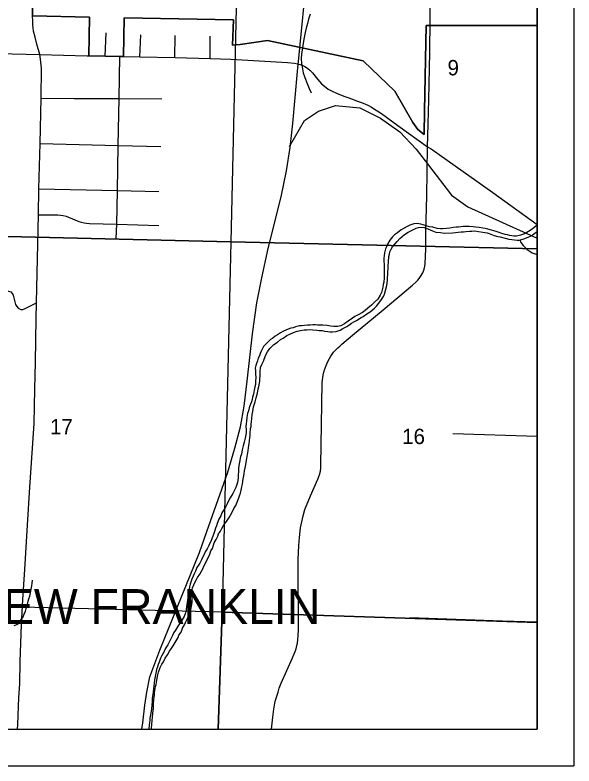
# Model space of a CAD drawing. Extents: x 0 to 34, y -5 to 22.
# Drawn here: x 7.476 to 9, y 14 to 16.047 of the extents above; entities that cross this region are included whole.
import ezdxf

# ---------------------------------------------------------------- set-up
doc = ezdxf.new("R2010")
doc.units = 0
for name, color, linetype in [('GM_X_City_Street', 7, 'Continuous'), ('GM_X_Corporation_Text', 7, 'Continuous'), ('GM_X_County_Road', 7, 'Continuous'), ('GM_X_Major_River', 7, 'Continuous'), ('GM_X_Minor_River', 7, 'Continuous'), ('GM_X_Rail_Line', 7, 'Continuous'), ('GM_X_Section', 7, 'Continuous'), ('GM_X_Section_Text', 7, 'Continuous'), ('GM_X_Township_Road', 7, 'Continuous'), ('GM_X_US_Route', 7, 'Continuous'), ('SC_Scratch2', 7, 'Continuous'), ('SH_Cut_Line', 7, 'Continuous'), ('SH_Data', 7, 'Continuous')]:
    doc.layers.add(name, color=color, linetype=linetype)

msp = doc.modelspace()

# ---------------------------------------------------------------- linework, layer by layer
at = {"layer": 'GM_X_City_Street'}
for points in [[(8.9, 15.4101), (8.9, 16.4107), (8.0868, 16.4255), (8.0646, 15.4287)], [(8.9, 14.3911), (8.9, 15.4101), (8.0646, 15.4287), (8.041, 14.419)], [(6.9745, 14.1), (8.0304, 14.1), (8.041, 14.419), (6.9822, 14.4457)], [(8.0304, 14.1), (8.9, 14.1), (8.9, 14.3911), (8.041, 14.419)]]:
    msp.add_lwpolyline(points, close=True, dxfattribs=at)
at = {"layer": 'GM_X_County_Road'}
for p, q in [((7.5439, 15.9397), (7.6724, 15.9357)), ((8.6006, 15.688), (8.6014, 15.7176))]:
    msp.add_line(p, q, dxfattribs=at)
for points in [[(8.6066, 15.9447), (8.6069, 15.9615), (8.6077, 16.0182), (8.6081, 16.1361), (8.6122, 16.2981), (8.6134, 16.3612), (8.6129, 16.3779)], [(7.5238, 16.047), (7.5244, 16.0747), (7.525, 16.0968), (7.5286, 16.2498), (7.5306, 16.3351)], [(7.5439, 15.9397), (7.5358, 15.9674), (7.5307, 15.9865), (7.5265, 16.0032), (7.5252, 16.012), (7.5243, 16.0205), (7.5243, 16.0309), (7.5237, 16.044), (7.5238, 16.047)], [(6.9889, 15.9539), (7.2426, 15.947), (7.5439, 15.9397)], [(7.535, 15.2621), (7.5384, 15.4231), (7.54, 15.5026), (7.5413, 15.5729), (7.5445, 15.6966), (7.547, 15.8205), (7.5482, 15.9022), (7.5468, 15.9185), (7.5457, 15.927), (7.5439, 15.9397)], [(7.6724, 15.9357), (7.6773, 15.9356), (7.7222, 15.9348), (7.7622, 15.9337), (7.772, 15.9336), (7.7731, 15.9336)], [(7.7731, 15.9336), (7.8165, 15.9333), (7.9119, 15.9309), (8.0077, 15.9284), (8.0643, 15.9268), (8.219, 15.9176), (8.2379, 15.9156), (8.2459, 15.9142), (8.2532, 15.9124), (8.2591, 15.9101), (8.2666, 15.9066), (8.2736, 15.9022), (8.2803, 15.8965), (8.2872, 15.8895), (8.3009, 15.8718), (8.3119, 15.8592), (8.3196, 15.8527), (8.3294, 15.8453), (8.3349, 15.8421), (8.3408, 15.8392), (8.3522, 15.8339), (8.3722, 15.8262), (8.3838, 15.8221), (8.3958, 15.8176), (8.407, 15.8135), (8.4184, 15.8095), (8.43, 15.8048), (8.4394, 15.8005), (8.4482, 15.7956), (8.461, 15.7877), (8.4749, 15.7783), (8.5197, 15.7457), (8.6006, 15.688)], [(8.6014, 15.7176), (8.6043, 15.8162), (8.6066, 15.9447)], [(8.1753, 14.1), (8.1754, 14.1001), (8.1788, 14.1327), (8.1819, 14.1552), (8.1847, 14.1712), (8.1866, 14.1796), (8.1892, 14.188), (8.1931, 14.2008), (8.1961, 14.212), (8.2018, 14.2254), (8.2328, 14.2951), (8.2371, 14.3055), (8.2397, 14.312), (8.2424, 14.3192), (8.2448, 14.3281), (8.2461, 14.3347), (8.2473, 14.3444), (8.2481, 14.3559), (8.2487, 14.3715), (8.2487, 14.3927), (8.2483, 14.5327), (8.2481, 14.5629), (8.2497, 14.6014), (8.2514, 14.623), (8.2542, 14.6489), (8.2613, 14.6815), (8.2664, 14.6994), (8.2815, 14.7363), (8.3019, 14.7815), (8.3066, 14.7939), (8.3088, 14.8033), (8.3096, 14.8121), (8.31, 14.8202), (8.3123, 14.9867), (8.3135, 15.0454), (8.3164, 15.0655), (8.3188, 15.0769), (8.3241, 15.092), (8.3298, 15.1045), (8.3371, 15.1167), (8.3445, 15.1277), (8.3559, 15.1401), (8.3622, 15.1456), (8.367, 15.1502), (8.3964, 15.1745), (8.4794, 15.2434), (8.5602, 15.3109), (8.5696, 15.3198), (8.5741, 15.3241), (8.578, 15.3292), (8.5816, 15.3341), (8.5876, 15.3439), (8.5912, 15.3545), (8.5933, 15.3622), (8.5941, 15.3689), (8.5961, 15.4099), (8.5961, 15.4557), (8.5986, 15.5531), (8.6006, 15.688)], [(8.6006, 15.688), (8.6106, 15.6819), (8.7785, 15.5635), (8.9, 15.4759)], [(7.4833, 14.1), (7.4837, 14.1131), (7.4849, 14.1379), (7.4868, 14.1864), (7.4888, 14.2237), (7.4904, 14.285), (7.4939, 14.3849), (7.4971, 14.4534), (7.5029, 14.5355), (7.5104, 14.6563), (7.5167, 14.7596), (7.5212, 14.8262), (7.5279, 14.9338), (7.53, 15.0275), (7.5316, 15.1011), (7.534, 15.2197), (7.535, 15.2621)]]:
    msp.add_lwpolyline(points, dxfattribs=at)
at = {"layer": 'GM_X_Major_River'}
for points in [[(8.9, 15.4741), (8.8956, 15.4714), (8.8858, 15.4637), (8.8756, 15.4568), (8.865, 15.4506), (8.8544, 15.447), (8.8431, 15.4443), (8.8362, 15.4442), (8.8252, 15.4463), (8.8187, 15.4474), (8.8127, 15.4489), (8.8032, 15.4514), (8.7933, 15.4547), (8.7875, 15.4566), (8.775, 15.4603), (8.7655, 15.4632), (8.7582, 15.4654), (8.7514, 15.4661), (8.7415, 15.4675), (8.7316, 15.4685), (8.7248, 15.4692), (8.7145, 15.4706), (8.7035, 15.4705), (8.6979, 15.4701), (8.6914, 15.4696), (8.685, 15.4688), (8.6789, 15.4684), (8.6702, 15.4675), (8.6611, 15.4663), (8.6527, 15.4647), (8.6414, 15.4638), (8.6357, 15.4641), (8.6273, 15.4655), (8.6155, 15.4688), (8.6064, 15.4699), (8.5969, 15.4724), (8.5889, 15.475), (8.5828, 15.4772), (8.5714, 15.4786), (8.5631, 15.4782), (8.5521, 15.4739), (8.5453, 15.4707), (8.5291, 15.4611), (8.5185, 15.4537), (8.511, 15.448), (8.5053, 15.4422), (8.4982, 15.433), (8.4919, 15.4227), (8.4889, 15.4151), (8.4863, 15.4093), (8.4838, 15.3987), (8.4827, 15.3914), (8.482, 15.3846), (8.4822, 15.3591), (8.4823, 15.3523), (8.4825, 15.331), (8.4815, 15.3188), (8.48, 15.3124), (8.4786, 15.3051), (8.4768, 15.2983), (8.4749, 15.2907), (8.4712, 15.283), (8.4656, 15.2727), (8.4566, 15.2639), (8.4476, 15.2558), (8.4378, 15.2481), (8.4303, 15.2419), (8.4231, 15.2362), (8.4114, 15.23), (8.4027, 15.2249), (8.3963, 15.2207), (8.3846, 15.2129), (8.3741, 15.2052), (8.3642, 15.2002), (8.3552, 15.1978), (8.3453, 15.1981), (8.3362, 15.1991), (8.3271, 15.2009)], [(8.3515, 15.1841), (8.3621, 15.188), (8.3696, 15.1923), (8.3806, 15.1981), (8.3866, 15.202), (8.3938, 15.2066), (8.4002, 15.2108), (8.407, 15.2147), (8.4194, 15.2221), (8.4255, 15.2255), (8.4349, 15.2321), (8.4443, 15.2383), (8.456, 15.2483), (8.462, 15.2533), (8.4703, 15.2652), (8.4751, 15.2717), (8.4804, 15.2797), (8.4837, 15.2858), (8.487, 15.2995), (8.4885, 15.306), (8.4903, 15.3151), (8.4913, 15.325), (8.4926, 15.3456), (8.4933, 15.3577), (8.4936, 15.3646), (8.4939, 15.3733), (8.4956, 15.3885), (8.4971, 15.3954), (8.4982, 15.4011), (8.5019, 15.4084), (8.5056, 15.4152), (8.512, 15.4225), (8.5176, 15.4294), (8.5255, 15.4382), (8.5379, 15.4483), (8.5481, 15.4548), (8.5606, 15.4614), (8.5696, 15.4657), (8.5761, 15.4677), (8.5855, 15.4685), (8.5912, 15.4674), (8.5973, 15.4656), (8.608, 15.4619), (8.6141, 15.4589), (8.6236, 15.4552), (8.6358, 15.4538), (8.6464, 15.4528), (8.6688, 15.4531), (8.6768, 15.4539), (8.684, 15.4547), (8.6923, 15.4556), (8.6987, 15.4564), (8.7048, 15.4572), (8.7154, 15.4577), (8.7211, 15.4582), (8.7295, 15.4583), (8.7393, 15.4572), (8.7511, 15.4551), (8.7568, 15.454), (8.7633, 15.4529), (8.7736, 15.45), (8.7823, 15.4463), (8.7926, 15.4437), (8.7987, 15.4426), (8.8124, 15.4386), (8.8223, 15.4364), (8.8306, 15.435), (8.8375, 15.4343), (8.8447, 15.4336), (8.8508, 15.4337), (8.8568, 15.4349), (8.8629, 15.4365), (8.8754, 15.4412), (8.8829, 15.4454), (8.8935, 15.4524), (8.9, 15.4569)], [(8.3271, 15.2009), (8.3149, 15.202), (8.3012, 15.2018), (8.2955, 15.2021), (8.2883, 15.2021), (8.2807, 15.202), (8.2735, 15.2015), (8.2656, 15.2007), (8.2572, 15.2002), (8.2516, 15.1994), (8.2409, 15.1974), (8.2341, 15.1946), (8.2277, 15.1931), (8.2164, 15.1888), (8.2065, 15.1841), (8.2001, 15.1806), (8.1918, 15.1752), (8.1854, 15.1717), (8.179, 15.1663), (8.173, 15.1621), (8.1628, 15.1528), (8.1538, 15.1433), (8.1471, 15.1303), (8.1445, 15.1242), (8.1423, 15.1184), (8.1389, 15.1116), (8.1371, 15.1047), (8.1341, 15.0974), (8.1323, 15.0917), (8.1312, 15.0841), (8.1313, 15.0784), (8.1318, 15.0678), (8.1322, 15.0598), (8.132, 15.0484), (8.1313, 15.04), (8.1302, 15.0336), (8.1284, 15.0241), (8.1262, 15.0138), (8.124, 15.005), (8.1226, 14.9993), (8.1204, 14.9924), (8.1185, 14.986), (8.1148, 14.9764), (8.1122, 14.9684), (8.11, 14.9604), (8.1083, 14.9497), (8.1072, 14.9402), (8.1061, 14.9322), (8.1054, 14.9262), (8.1063, 14.9167), (8.106, 14.9079), (8.1046, 14.8984), (8.1024, 14.8897), (8.1006, 14.8824), (8.0984, 14.8729), (8.0958, 14.8622), (8.0933, 14.8504), (8.0911, 14.8436), (8.0882, 14.8283), (8.0867, 14.8188), (8.0857, 14.8112), (8.0854, 14.8036), (8.0847, 14.7926), (8.0844, 14.7857), (8.0823, 14.7728), (8.0778, 14.7591), (8.0741, 14.7522), (8.0697, 14.7426), (8.0629, 14.7308), (8.0585, 14.7224), (8.0547, 14.7144), (8.0495, 14.7059), (8.045, 14.6979), (8.0402, 14.6903), (8.0369, 14.6815), (8.032, 14.6731), (8.0276, 14.6613), (8.025, 14.6548), (8.0231, 14.6487), (8.0205, 14.6422), (8.018, 14.6338), (8.015, 14.6266), (8.0109, 14.6147), (8.0042, 14.601), (7.9998, 14.5922), (7.9949, 14.5838), (7.9916, 14.5765), (7.9882, 14.57), (7.9841, 14.562), (7.9797, 14.5532), (7.9763, 14.5475), (7.9718, 14.5414), (7.9681, 14.5314), (7.9648, 14.5234), (7.9618, 14.5173), (7.9581, 14.5093), (7.9555, 14.5013), (7.954, 14.4952), (7.9522, 14.4883), (7.9501, 14.4746), (7.949, 14.4682)], [(7.9492, 14.4085), (7.9529, 14.4184), (7.9551, 14.4268), (7.9573, 14.436), (7.9587, 14.4455), (7.9584, 14.4743), (7.9591, 14.4801), (7.9602, 14.4858), (7.9632, 14.4934), (7.9676, 14.5022), (7.971, 14.5079), (7.974, 14.5137), (7.9799, 14.5228), (7.9848, 14.5312), (7.9878, 14.537), (7.9907, 14.5446), (7.9971, 14.5568), (8.003, 14.5687), (8.006, 14.5748), (8.0101, 14.5862), (8.0142, 14.5931), (8.0175, 14.6015), (8.0193, 14.6087), (8.0246, 14.6172), (8.0287, 14.6263), (8.0309, 14.6328), (8.0365, 14.6397), (8.0402, 14.6477), (8.0458, 14.6573), (8.0526, 14.6668), (8.06, 14.6776), (8.0638, 14.6837), (8.0697, 14.6955), (8.0731, 14.702), (8.0779, 14.7104), (8.0813, 14.7192), (8.0865, 14.731), (8.0879, 14.7368), (8.0909, 14.7432), (8.0927, 14.752), (8.0945, 14.7608), (8.0963, 14.768), (8.0974, 14.7764), (8.0981, 14.7828), (8.0999, 14.7905), (8.1006, 14.7977), (8.1021, 14.8049), (8.1046, 14.816), (8.1064, 14.8285), (8.1078, 14.8384), (8.1096, 14.8487), (8.1114, 14.8594), (8.1128, 14.8685), (8.1146, 14.8784), (8.1153, 14.8871), (8.1164, 14.8944), (8.1171, 14.9008), (8.1174, 14.9069), (8.1184, 14.9195), (8.1195, 14.9252), (8.1198, 14.9313), (8.1205, 14.9377), (8.1216, 14.9469), (8.1226, 14.9583), (8.1244, 14.9666), (8.1266, 14.9792), (8.131, 14.9929), (8.1339, 15.0036), (8.1376, 15.0162), (8.1394, 15.0276), (8.1416, 15.0379), (8.1437, 15.0501), (8.1443, 15.0691), (8.1442, 15.0751), (8.1456, 15.0858), (8.1486, 15.0946), (8.1531, 15.1037), (8.159, 15.119), (8.1646, 15.1289), (8.1709, 15.1377), (8.1815, 15.1485), (8.192, 15.1554), (8.1999, 15.1627), (8.2075, 15.1666), (8.2169, 15.1732), (8.2252, 15.1771), (8.2354, 15.1814), (8.2449, 15.1849), (8.254, 15.1869), (8.2642, 15.1885), (8.2721, 15.1893), (8.2782, 15.1894), (8.2881, 15.1891), (8.2987, 15.1881), (8.3052, 15.1874), (8.3139, 15.1867), (8.3196, 15.1853), (8.3287, 15.1842), (8.3344, 15.1835), (8.3416, 15.1836), (8.3515, 15.1841)], [(7.949, 14.4682), (7.9472, 14.4579), (7.9454, 14.4453), (7.944, 14.4351), (7.9426, 14.4248), (7.9411, 14.4176), (7.9374, 14.4073), (7.9303, 14.3958), (7.9262, 14.3893), (7.9217, 14.3835), (7.9139, 14.3698), (7.9094, 14.364), (7.9057, 14.356), (7.9012, 14.3465), (7.8956, 14.3361), (7.8926, 14.3304), (7.8859, 14.3189), (7.8826, 14.3121), (7.8792, 14.3059), (7.8759, 14.2995), (7.8729, 14.2937), (7.8692, 14.2827), (7.8666, 14.2762), (7.8648, 14.2701), (7.8622, 14.2628), (7.86, 14.2529), (7.8582, 14.2442), (7.8564, 14.235), (7.8553, 14.2251), (7.8543, 14.2183), (7.8539, 14.2111), (7.8525, 14.2012), (7.8515, 14.1947), (7.8504, 14.1848), (7.8501, 14.1761), (7.8495, 14.1654), (7.8484, 14.1555), (7.8473, 14.1491), (7.8455, 14.1392), (7.8441, 14.13), (7.8434, 14.1243), (7.8427, 14.1182), (7.8416, 14.1114), (7.8406, 14.1019), (7.8403, 14.1)], [(7.8483, 14.1), (7.8485, 14.1031), (7.8492, 14.113), (7.8499, 14.1244), (7.8505, 14.1331), (7.8516, 14.1434), (7.8533, 14.1586), (7.854, 14.1681), (7.855, 14.1818), (7.856, 14.1925), (7.8567, 14.1982), (7.8574, 14.2054), (7.8592, 14.2164), (7.8607, 14.2225), (7.8625, 14.2332), (7.8635, 14.2397), (7.8653, 14.2484), (7.8676, 14.2561), (7.872, 14.2683), (7.8768, 14.2778), (7.8806, 14.2843), (7.8858, 14.2935), (7.8914, 14.303), (7.8977, 14.3126), (7.9022, 14.3195), (7.9075, 14.3271), (7.9157, 14.3409), (7.9205, 14.3501), (7.9224, 14.3562), (7.9287, 14.365), (7.9324, 14.376), (7.9384, 14.3848), (7.9406, 14.3913), (7.9451, 14.4005), (7.9492, 14.4085)]]:
    msp.add_lwpolyline(points, dxfattribs=at)
at = {"layer": 'GM_X_Minor_River'}
for points in [[(8.2806, 16.0497), (8.2761, 16.0356), (8.2732, 16.0241), (8.2699, 16.0116), (8.2674, 15.9994), (8.2641, 15.9857), (8.263, 15.9754), (8.2609, 15.964), (8.2587, 15.9514), (8.2573, 15.9411), (8.2563, 15.9278), (8.2572, 15.9146), (8.2596, 15.9005), (8.262, 15.8892), (8.2663, 15.8767), (8.2725, 15.86), (8.2776, 15.8468), (8.2838, 15.8351)], [(8.8527, 15.4341), (8.855, 15.4265), (8.8615, 15.419), (8.8723, 15.4081), (8.878, 15.404), (8.886, 15.3991), (8.8917, 15.3965), (8.9, 15.3943)], [(7.4736, 14.383), (7.4834, 14.3869), (7.4905, 14.3953), (7.4973, 14.4045), (7.501, 14.414), (7.5043, 14.4224), (7.5065, 14.4293), (7.5098, 14.4403), (7.5124, 14.4491), (7.5142, 14.4552), (7.5164, 14.4632), (7.5182, 14.4724), (7.52, 14.4819), (7.5218, 14.491), (7.5229, 14.4979), (7.5236, 14.5066)]]:
    msp.add_lwpolyline(points, dxfattribs=at)
at = {"layer": 'GM_X_Rail_Line'}
for points in [[(7.8219, 14.1), (7.8245, 14.1172), (7.83, 14.1656), (7.8351, 14.2014), (7.8436, 14.2434), (7.871, 14.3158), (7.9793, 14.5821), (7.9989, 14.6392), (8.0557, 14.7979), (8.0753, 14.8664), (8.0908, 14.9248), (8.101, 14.981), (8.109, 15.049), (8.1233, 15.1783), (8.1356, 15.2629), (8.1491, 15.331), (8.1664, 15.4103), (8.2014, 15.5514), (8.2159, 15.6219), (8.2266, 15.6862), (8.2335, 15.7512), (8.2459, 15.8933), (8.2766, 16.1971)], [(8.2243, 15.6885), (8.2655, 15.7598), (8.3031, 15.7849), (8.35, 15.8005), (8.4158, 15.7942), (8.4722, 15.766), (8.5255, 15.7283), (8.5693, 15.6813), (8.6037, 15.6374), (8.6664, 15.5559), (8.7102, 15.5245), (8.9, 15.4383)]]:
    msp.add_lwpolyline(points, dxfattribs=at)
at = {"layer": 'GM_X_Section'}
for points in [[(7.0252, 16.4555), (8.0868, 16.4255), (8.0646, 15.4287), (6.9989, 15.4538)], [(8.0646, 15.4287), (8.041, 14.419), (6.9822, 14.4457), (6.9989, 15.4538)]]:
    msp.add_lwpolyline(points, close=True, dxfattribs=at)
at = {"layer": 'GM_X_Township_Road'}
for p, q in [((7.7222, 15.9348), (7.7243, 15.9987)), ((7.8165, 15.9333), (7.8188, 15.9934)), ((7.9119, 15.9309), (7.9131, 15.9916)), ((8.0077, 15.9284), (8.0077, 15.9898)), ((8.6697, 14.9065), (8.9, 14.8987))]:
    msp.add_line(p, q, dxfattribs=at)
for points in [[(7.7521, 15.4378), (7.7534, 15.4769), (7.7552, 15.569), (7.7572, 15.6917), (7.7601, 15.8194), (7.7622, 15.9337)], [(7.547, 15.8205), (7.637, 15.8195), (7.7601, 15.8194), (7.876, 15.8188)], [(7.5445, 15.6966), (7.7572, 15.6917), (7.8736, 15.689)], [(7.5413, 15.5729), (7.7552, 15.569), (7.8683, 15.566)], [(7.54, 15.5026), (7.5924, 15.5024), (7.5999, 15.5018), (7.6075, 15.5008), (7.6152, 15.4989), (7.6215, 15.4963), (7.6499, 15.4843), (7.6564, 15.4822), (7.6645, 15.4806), (7.6711, 15.4796), (7.6792, 15.4786), (7.7534, 15.4769), (7.8679, 15.4737)], [(7.0008, 15.2663), (7.0094, 15.2661), (7.0224, 15.2676), (7.0505, 15.2702), (7.0776, 15.2737), (7.1025, 15.2763), (7.1353, 15.2792), (7.1543, 15.281), (7.2007, 15.2835), (7.267, 15.2845), (7.3797, 15.2879), (7.4387, 15.2938), (7.4521, 15.2949), (7.4584, 15.2943), (7.4645, 15.2926), (7.4686, 15.2883), (7.4713, 15.2831), (7.4778, 15.2576), (7.481, 15.2521), (7.4851, 15.2476), (7.4918, 15.2439), (7.4973, 15.2439), (7.5037, 15.2466), (7.535, 15.2621)], [(8.5521, 14.4049), (8.8052, 14.3955), (8.8667, 14.3939), (8.9, 14.3925)]]:
    msp.add_lwpolyline(points, dxfattribs=at)
at = {"layer": 'GM_X_US_Route'}
msp.add_lwpolyline([(6.156, 14.1), (8.9, 14.1), (8.9, 16.5981)], dxfattribs=at)
at = {"layer": 'SC_Scratch2'}
for points in [[(6.156, 14.1), (8.9, 14.1), (8.9, 16.0187), (8.6075, 16.0188), (8.5972, 16.0188), (8.5927, 15.7854), (8.5916, 15.7217), (8.5742, 15.7348), (8.5611, 15.7542), (8.5113, 15.8392), (8.4261, 15.9215), (8.4253, 15.922), (8.1648, 15.9775), (8.0903, 15.9671), (8.0689, 15.9644), (8.0713, 16.0342), (7.7737, 16.0396), (7.7718, 15.9342), (7.722, 15.9353), (7.6771, 15.9361), (7.679, 16.0414), (7.5235, 16.0445), (7.5248, 16.0973)], [(7.5248, 16.0973), (7.5235, 16.0445), (7.679, 16.0414), (7.6771, 15.9361), (7.722, 15.9353), (7.7718, 15.9342), (7.7737, 16.0396), (8.0713, 16.0342), (8.0689, 15.9644), (8.0903, 15.9671), (8.1648, 15.9775), (8.4253, 15.922), (8.4261, 15.9215), (8.5113, 15.8392), (8.5611, 15.7542), (8.5742, 15.7348), (8.5916, 15.7217), (8.5927, 15.7854), (8.5972, 16.0188), (8.6075, 16.0188), (8.9, 16.0187), (8.9, 16.0675)]]:
    msp.add_lwpolyline(points, dxfattribs=at)
at = {"layer": 'SH_Cut_Line'}
msp.add_lwpolyline([(6.156, 14.1), (8.9, 14.1), (8.9, 20.9)], dxfattribs=at)
at = {"layer": 'SH_Data'}
for p, q in [((9, 21), (9, 14)), ((8.9, 20.9), (8.9, 14.1)), ((2.1, 14.1), (8.9, 14.1)), ((2, 14), (9, 14))]:
    msp.add_line(p, q, dxfattribs=at)

# ---------------------------------------------------------------- texts
at = {"layer": 'GM_X_Corporation_Text'}
msp.add_text('NEW FRANKLIN', height=0.094697, rotation=0, dxfattribs=at).set_placement((7.3516, 14.3873))
at = {"layer": 'GM_X_Section_Text'}
for s, height, p in [('9', 0.0419, (8.6552, 15.8825)), ('17', 0.04186, (7.5715, 14.9038)), ('16', 0.04186, (8.5315, 14.8775))]:
    msp.add_text(s, height=height, rotation=0, dxfattribs=at).set_placement(p)

doc.saveas('drawing.dxf')
